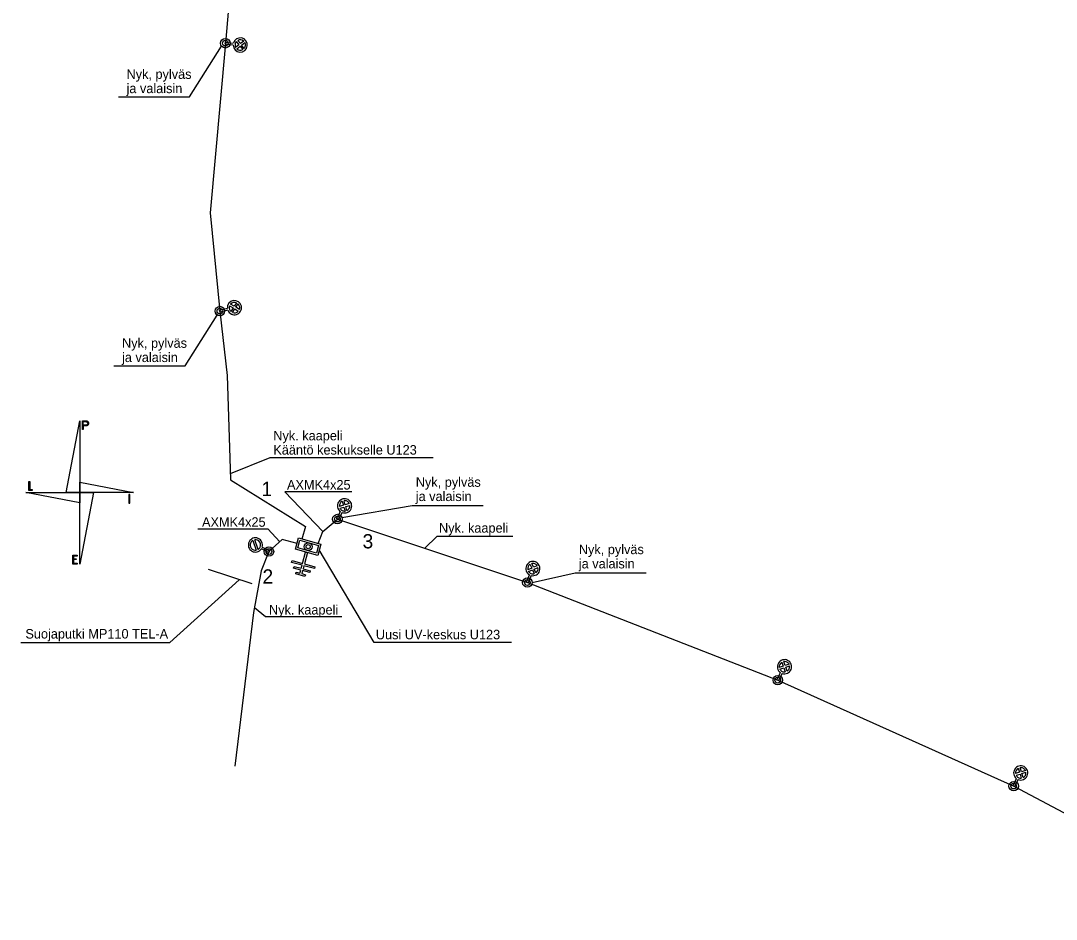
# Model space of a CAD drawing. Extents: x 25497852 to 25498297, y 6686544 to 6687252.
# Drawn here: x 25497911.2 to 25498074.6, y 6686966.9 to 6687108.7 of the extents above; entities that cross this region are included whole.
import ezdxf

# ---------------------------------------------------------------- set-up
doc = ezdxf.new("R2010")
doc.units = 0
for name, color, linetype in [('KayttoOikeusYksikko_piste_tunnus', 7, 'Continuous'), ('KiinteistoNimi', 7, 'Continuous'), ('Raja', 7, 'Continuous'), ('Rajamerkki_tonttipyykki', 7, 'Continuous'), ('Rasitealue', 7, 'Continuous'), ('Rasiteviiva', 7, 'Continuous'), ('Taso 1', 7, 'Continuous'), ('VuokraAlue', 7, 'Continuous')]:
    doc.layers.add(name, color=color, linetype=linetype)

msp = doc.modelspace()

# ---------------------------------------------------------------- linework, layer by layer
at = {"layer": 'KayttoOikeusYksikko_piste_tunnus'}
for p, q in [((25497945.83, 6687105.07), (25497945.42, 6687105.59)), ((25497943.43, 6687104.98), (25497943.47, 6687105.28)), ((25497944.68, 6687104.84), (25497943.43, 6687104.98)), ((25497943.47, 6687105.28), (25497944.71, 6687105.13)), ((25497945.59, 6687104.88), (25497945.08, 6687104.47)), ((25497945.18, 6687105.4), (25497945.59, 6687104.88)), ((25497945.26, 6687104.24), (25497945.78, 6687104.65)), ((25497945.78, 6687104.65), (25497946.19, 6687104.13)), ((25497946.35, 6687105.48), (25497945.83, 6687105.07)), ((25497946.02, 6687104.83), (25497946.53, 6687105.24)), ((25497946.43, 6687104.31), (25497946.02, 6687104.83)), ((25497942.55, 6687063), (25497943.77, 6687063.29)), ((25497944.13, 6687063.7), (25497944.69, 6687063.35)), ((25497944.85, 6687063.61), (25497944.28, 6687063.95)), ((25497944.69, 6687063.35), (25497944.34, 6687062.79)), ((25497944.59, 6687062.63), (25497944.94, 6687063.19)), ((25497945.19, 6687064.17), (25497944.85, 6687063.61)), ((25497944.94, 6687063.19), (25497945.5, 6687062.84)), ((25497945.1, 6687063.45), (25497945.45, 6687064.01)), ((25497945.66, 6687063.1), (25497945.1, 6687063.45)), ((25497942.62, 6687062.71), (25497942.55, 6687063)), ((25497943.84, 6687063), (25497942.62, 6687062.71)), ((25497962.08, 6687032.21), (25497961.45, 6687032.02)), ((25497961.89, 6687032.84), (25497962.08, 6687032.21)), ((25497962.37, 6687032.29), (25497962.18, 6687032.93)), ((25497963, 6687032.48), (25497962.37, 6687032.29)), ((25497962.45, 6687032.01), (25497963.09, 6687032.19)), ((25497962.64, 6687031.37), (25497962.45, 6687032.01)), ((25497961, 6687030.1), (25497961.6, 6687031.2)), ((25497961.86, 6687031.06), (25497961.26, 6687029.96)), ((25497961.53, 6687031.74), (25497962.16, 6687031.92)), ((25497962.16, 6687031.92), (25497962.35, 6687031.29)), ((25497961.26, 6687029.96), (25497961, 6687030.1)), ((25497947.8, 6687026.66), (25497948.32, 6687025.13)), ((25497948.61, 6687025.22), (25497948.08, 6687026.76)), ((25497949.27, 6687025.59), (25497950.4, 6687025.03)), ((25497950.26, 6687024.76), (25497949.14, 6687025.32)), ((25497950.4, 6687025.03), (25497950.26, 6687024.76)), ((25497991.79, 6687022.29), (25497991.18, 6687022.03)), ((25497991.52, 6687022.89), (25497991.79, 6687022.29)), ((25497992.06, 6687022.41), (25497991.8, 6687023.01)), ((25497992.67, 6687022.67), (25497992.06, 6687022.41)), ((25497992.18, 6687022.13), (25497992.79, 6687022.39)), ((25497990.97, 6687020.06), (25497991.43, 6687021.23)), ((25497991.71, 6687021.12), (25497991.25, 6687019.95)), ((25497991.3, 6687021.75), (25497991.91, 6687022.01)), ((25497991.91, 6687022.01), (25497992.17, 6687021.41)), ((25497992.44, 6687021.52), (25497992.18, 6687022.13)), ((25497991.25, 6687019.95), (25497990.97, 6687020.06)), ((25498031.77, 6687006.91), (25498031.56, 6687007.54)), ((25498031.49, 6687006.82), (25498030.86, 6687006.61)), ((25498030.95, 6687006.32), (25498031.58, 6687006.53)), ((25498031.27, 6687007.44), (25498031.49, 6687006.82)), ((25498031.58, 6687006.53), (25498031.79, 6687005.91)), ((25498032.4, 6687007.13), (25498031.77, 6687006.91)), ((25498031.87, 6687006.63), (25498032.49, 6687006.84)), ((25498032.08, 6687006), (25498031.87, 6687006.63)), ((25498030.49, 6687004.67), (25498031.05, 6687005.79)), ((25498030.76, 6687004.53), (25498030.49, 6687004.67)), ((25498031.32, 6687005.66), (25498030.76, 6687004.53)), ((25498068.77, 6686990.06), (25498068.14, 6686989.87)), ((25498068.23, 6686989.58), (25498068.86, 6686989.78)), ((25498068.58, 6686990.69), (25498068.77, 6686990.06)), ((25498068.86, 6686989.78), (25498069.05, 6686989.14)), ((25498069.06, 6686990.15), (25498068.87, 6686990.78)), ((25498069.69, 6686990.34), (25498069.06, 6686990.15)), ((25498069.15, 6686989.86), (25498069.78, 6686990.06)), ((25498069.34, 6686989.23), (25498069.15, 6686989.86)), ((25498067.71, 6686987.94), (25498068.3, 6686989.05)), ((25498067.98, 6686987.8), (25498067.71, 6686987.94)), ((25498068.57, 6686988.91), (25498067.98, 6686987.8))]:
    msp.add_line(p, q, dxfattribs=at)
for centre, radius, start, end in [((25497945.8, 6687104.86), 1.12, 353.4004, 165.7381), ((25497945.8, 6687104.86), 0.825, 48.876, 117.9247), ((25497945.8, 6687104.86), 1.12, 181.0626, 353.4004), ((25497945.8, 6687104.86), 0.825, 173.4004, 207.9247), ((25497945.8, 6687104.86), 0.825, 138.876, 173.4004), ((25497945.8, 6687104.86), 0.825, 228.876, 297.9247), ((25497945.8, 6687104.86), 0.825, 318.876, 353.4004), ((25497945.8, 6687104.86), 0.825, 353.4004, 27.9247), ((25497944.89, 6687063.4), 1.12, 13.2418, 185.5795), ((25497944.89, 6687063.4), 1.12, 200.904, 13.2418), ((25497944.89, 6687063.4), 0.825, 158.7175, 193.2418), ((25497944.89, 6687063.4), 0.825, 193.2418, 227.7661), ((25497944.89, 6687063.4), 0.825, 68.7175, 137.7661), ((25497944.89, 6687063.4), 0.825, 13.2418, 47.7661), ((25497944.89, 6687063.4), 0.825, 338.7175, 13.2418), ((25497944.89, 6687063.4), 0.825, 248.7175, 317.7661), ((25497962.27, 6687032.11), 1.12, 61.3434, 233.6812), ((25497962.27, 6687032.11), 0.825, 116.8191, 185.8678), ((25497962.27, 6687032.11), 1.12, 249.0057, 61.3434), ((25497962.27, 6687032.11), 0.825, 61.3434, 95.8678), ((25497962.27, 6687032.11), 0.825, 296.8191, 5.8678), ((25497962.27, 6687032.11), 0.825, 26.8191, 61.3434), ((25497962.27, 6687032.11), 0.825, 206.8191, 241.3434), ((25497962.27, 6687032.11), 0.825, 241.3434, 275.8678), ((25497948.2, 6687025.94), 1.12, 341.5217, 153.8595), ((25497948.2, 6687025.94), 1.12, 153.8595, 326.1972), ((25497948.2, 6687025.94), 0.825, 153.8595, 278.3838), ((25497948.2, 6687025.94), 0.825, 119.3352, 153.8595), ((25497948.2, 6687025.94), 0.825, 333.8595, 98.3838), ((25497948.2, 6687025.94), 0.825, 299.3352, 333.8595), ((25497991.98, 6687022.21), 1.12, 68.4031, 240.7408), ((25497991.98, 6687022.21), 0.825, 123.8788, 192.9274), ((25497991.98, 6687022.21), 1.12, 256.0653, 68.4031), ((25497991.98, 6687022.21), 0.825, 68.4031, 102.9274), ((25497991.98, 6687022.21), 0.825, 33.8788, 68.4031), ((25497991.98, 6687022.21), 0.825, 303.8788, 12.9274), ((25497991.98, 6687022.21), 0.825, 213.8788, 248.4031), ((25497991.98, 6687022.21), 0.825, 248.4031, 282.9274), ((25498031.68, 6687006.72), 1.12, 63.6694, 236.0071), ((25498031.68, 6687006.72), 1.12, 251.3316, 63.6694), ((25498031.68, 6687006.72), 0.825, 63.6694, 98.1937), ((25498031.68, 6687006.72), 0.825, 29.145, 63.6694), ((25498031.68, 6687006.72), 0.825, 119.145, 188.1937), ((25498031.68, 6687006.72), 0.825, 209.145, 243.6694), ((25498031.68, 6687006.72), 0.825, 243.6694, 278.1937), ((25498031.68, 6687006.72), 0.825, 299.145, 8.1937), ((25498068.96, 6686989.96), 1.12, 61.9449, 234.2826), ((25498068.96, 6686989.96), 0.825, 117.4206, 186.4692), ((25498068.96, 6686989.96), 0.825, 207.4206, 241.9449), ((25498068.96, 6686989.96), 1.12, 249.6071, 61.9449), ((25498068.96, 6686989.96), 0.825, 61.9449, 96.4692), ((25498068.96, 6686989.96), 0.825, 297.4206, 6.4692), ((25498068.96, 6686989.96), 0.825, 27.4206, 61.9449), ((25498068.96, 6686989.96), 0.825, 241.9449, 276.4692)]:
    msp.add_arc(centre, radius, start, end, dxfattribs=at)
at = {"layer": 'KiinteistoNimi'}
for centre, radius in [((25497943.45, 6687105.13), 0.75), ((25497943.45, 6687105.13), 0.45), ((25497942.59, 6687062.86), 0.75), ((25497942.59, 6687062.86), 0.45), ((25497961.13, 6687030.03), 0.75), ((25497961.13, 6687030.03), 0.45), ((25497950.33, 6687024.9), 0.75), ((25497950.33, 6687024.9), 0.45), ((25497991.11, 6687020.01), 0.75), ((25497991.11, 6687020.01), 0.45), ((25498030.62, 6687004.6), 0.75), ((25498030.62, 6687004.6), 0.45), ((25498067.85, 6686987.87), 0.75), ((25498067.85, 6686987.87), 0.45)]:
    msp.add_circle(centre, radius, dxfattribs=at)
at = {"layer": 'Raja'}
msp.add_line((25497947.71, 6687019.79), (25497940.77, 6687022.09), dxfattribs=at)
at = {"layer": 'Rajamerkki_tonttipyykki'}
for p, q in [((25497912.44, 6687035.95), (25497912.58, 6687035.95)), ((25497912.44, 6687034.56), (25497912.44, 6687035.95)), ((25497912.58, 6687035.95), (25497912.58, 6687034.7)), ((25497912.99, 6687034.56), (25497912.44, 6687034.56)), ((25497912.58, 6687034.7), (25497912.99, 6687034.7)), ((25497912.99, 6687034.7), (25497912.99, 6687034.56)), ((25497919.37, 6687024.32), (25497920.06, 6687024.32)), ((25497919.37, 6687022.93), (25497919.37, 6687024.32)), ((25497920.06, 6687024.18), (25497919.51, 6687024.18)), ((25497919.51, 6687024.18), (25497919.51, 6687023.76)), ((25497920.06, 6687024.32), (25497920.06, 6687024.18)), ((25497955.64, 6687023.03), (25497956.12, 6687024.82)), ((25497956.41, 6687024.74), (25497955.93, 6687022.96)), ((25497956.12, 6687024.82), (25497956.41, 6687024.74)), ((25497920.06, 6687022.93), (25497919.37, 6687022.93)), ((25497919.51, 6687023.76), (25497919.92, 6687023.76)), ((25497919.92, 6687023.62), (25497919.51, 6687023.62)), ((25497919.51, 6687023.62), (25497919.51, 6687023.07)), ((25497919.51, 6687023.07), (25497920.06, 6687023.07)), ((25497919.92, 6687023.76), (25497919.92, 6687023.62)), ((25497920.06, 6687023.07), (25497920.06, 6687022.93)), ((25497953.89, 6687023.19), (25497953.97, 6687023.48)), ((25497955.56, 6687022.74), (25497953.89, 6687023.19)), ((25497953.97, 6687023.48), (25497955.64, 6687023.03)), ((25497954.23, 6687022.27), (25497954.31, 6687022.56)), ((25497955.35, 6687021.97), (25497954.23, 6687022.27)), ((25497954.31, 6687022.56), (25497955.43, 6687022.26)), ((25497955.43, 6687022.26), (25497955.56, 6687022.74)), ((25497955.85, 6687022.67), (25497955.72, 6687022.18)), ((25497955.72, 6687022.18), (25497956.84, 6687021.88)), ((25497957.51, 6687022.22), (25497955.85, 6687022.67)), ((25497955.93, 6687022.96), (25497957.59, 6687022.51)), ((25497957.59, 6687022.51), (25497957.51, 6687022.22)), ((25497954.56, 6687021.36), (25497954.64, 6687021.64)), ((25497956.01, 6687020.96), (25497954.56, 6687021.36)), ((25497954.64, 6687021.64), (25497955.22, 6687021.49)), ((25497955.22, 6687021.49), (25497955.35, 6687021.97)), ((25497955.64, 6687021.89), (25497955.51, 6687021.41)), ((25497955.51, 6687021.41), (25497956.09, 6687021.25)), ((25497956.76, 6687021.59), (25497955.64, 6687021.89)), ((25497956.09, 6687021.25), (25497956.01, 6687020.96)), ((25497956.84, 6687021.88), (25497956.76, 6687021.59))]:
    msp.add_line(p, q, dxfattribs=at)
for points in [[(25497918.33, 6687034.22), (25497920.48, 6687045.54), (25497920.48, 6687034.22)], [(25497920.48, 6687035.83), (25497928.97, 6687034.22), (25497920.48, 6687034.22)], [(25497920.48, 6687032.61), (25497911.99, 6687034.22), (25497920.48, 6687034.22)], [(25497922.63, 6687034.22), (25497920.48, 6687022.9), (25497920.48, 6687034.22)]]:
    msp.add_lwpolyline(points, close=True, dxfattribs=at)
for points in [[(25497920.9, 6687044.16), (25497920.9, 6687045.55), (25497921.46, 6687045.55)], [(25497921.04, 6687044.86), (25497921.04, 6687045.41), (25497921.46, 6687045.41)], [(25497921.46, 6687045.55), (25497921.5, 6687045.55), (25497921.54, 6687045.54), (25497921.58, 6687045.53), (25497921.62, 6687045.51), (25497921.66, 6687045.49), (25497921.7, 6687045.47), (25497921.73, 6687045.44), (25497921.76, 6687045.41), (25497921.79, 6687045.38), (25497921.81, 6687045.34), (25497921.83, 6687045.3), (25497921.85, 6687045.26), (25497921.86, 6687045.22), (25497921.87, 6687045.18), (25497921.87, 6687045.14), (25497921.87, 6687045.09), (25497921.86, 6687045.05), (25497921.85, 6687045.01), (25497921.83, 6687044.97), (25497921.81, 6687044.93), (25497921.79, 6687044.89), (25497921.76, 6687044.86), (25497921.73, 6687044.83), (25497921.7, 6687044.8), (25497921.66, 6687044.78), (25497921.62, 6687044.76), (25497921.58, 6687044.74), (25497921.54, 6687044.73), (25497921.5, 6687044.72), (25497921.46, 6687044.72)], [(25497921.46, 6687045.41), (25497921.48, 6687045.41), (25497921.51, 6687045.4), (25497921.54, 6687045.4), (25497921.57, 6687045.39), (25497921.59, 6687045.37), (25497921.62, 6687045.36), (25497921.64, 6687045.34), (25497921.66, 6687045.32), (25497921.68, 6687045.3), (25497921.69, 6687045.27), (25497921.71, 6687045.25), (25497921.72, 6687045.22), (25497921.73, 6687045.19), (25497921.73, 6687045.16), (25497921.73, 6687045.14), (25497921.73, 6687045.11), (25497921.73, 6687045.08), (25497921.72, 6687045.05), (25497921.71, 6687045.02), (25497921.69, 6687045), (25497921.68, 6687044.97), (25497921.66, 6687044.95), (25497921.64, 6687044.93), (25497921.62, 6687044.91), (25497921.59, 6687044.9), (25497921.57, 6687044.88), (25497921.54, 6687044.87), (25497921.51, 6687044.87), (25497921.48, 6687044.86), (25497921.46, 6687044.86)], [(25497921.46, 6687044.72), (25497921.04, 6687044.72), (25497921.04, 6687044.16), (25497920.9, 6687044.16)], [(25497921.46, 6687044.86), (25497921.04, 6687044.86)], [(25497928.22, 6687032.52), (25497928.36, 6687032.52), (25497928.36, 6687033.92), (25497928.22, 6687033.92), (25497928.22, 6687032.52)]]:
    msp.add_lwpolyline(points, dxfattribs=at)
at = {"layer": 'Rasitealue'}
for p, q in [((25497961.13, 6687030.03), (25497991.11, 6687020.01)), ((25497991.11, 6687020.01), (25498030.62, 6687004.6)), ((25498030.62, 6687004.6), (25498067.85, 6686987.87)), ((25498067.85, 6686987.87), (25498107.28, 6686966.85))]:
    msp.add_line(p, q, dxfattribs=at)
for points in [[(25497940.63, 6687135.56), (25497945.62, 6687130.39), (25497943.46, 6687105.16)], [(25497943.45, 6687105.13), (25497941.06, 6687078.34), (25497942.59, 6687062.85)], [(25497942.59, 6687062.86), (25497943.72, 6687052.67), (25497944.15, 6687039.66), (25497944.26, 6687036.24), (25497956.12, 6687028.87), (25497955.54, 6687026.88)], [(25497958.1, 6687026.15), (25497958.85, 6687028.05), (25497961.13, 6687030.03)], [(25497954.76, 6687026.17), (25497952.44, 6687026.79), (25497950.33, 6687024.9)], [(25497950.33, 6687024.9), (25497949.1, 6687021.84), (25497947.87, 6687015.26), (25497944.96, 6686991.03)]]:
    msp.add_lwpolyline(points, dxfattribs=at)
at = {"layer": 'Taso 1'}
for points in [[(25497926.59, 6687096.67), (25497937.82, 6687096.67), (25497942.85, 6687104.68)], [(25497925.88, 6687054.21), (25497937.11, 6687054.21), (25497942.14, 6687062.22)], [(25497976.24, 6687039.7), (25497950.48, 6687039.7), (25497944.23, 6687037.19)], [(25497963.4, 6687034.3), (25497952.86, 6687034.3), (25497958.85, 6687028.05)], [(25497984.15, 6687032.1), (25497972.92, 6687032.1), (25497961.84, 6687030.22)], [(25497939.1, 6687028.49), (25497950.13, 6687028.49), (25497952.05, 6687026.45)], [(25497988.79, 6687027.3), (25497976.82, 6687027.3), (25497974.91, 6687025.42)], [(25497988.58, 6687010.52), (25497966.91, 6687010.52), (25497958.27, 6687025.17)], [(25498009.88, 6687021.47), (25497998.65, 6687021.47), (25497991.86, 6687019.96)], [(25497911.16, 6687010.52), (25497934.71, 6687010.52), (25497945.65, 6687020.44)], [(25497961.83, 6687014.57), (25497949.79, 6687014.57), (25497948.03, 6687016.03)]]:
    msp.add_lwpolyline(points, dxfattribs=at)
at = {"layer": 'VuokraAlue'}
for p, q in [((25497954.51, 6687025.28), (25497955.01, 6687027.06)), ((25497954.88, 6687025.48), (25497955.22, 6687026.69)), ((25497957.81, 6687024.65), (25497954.88, 6687025.48)), ((25497955.01, 6687027.06), (25497958.52, 6687026.06)), ((25497955.22, 6687026.69), (25497958.15, 6687025.86)), ((25497958.15, 6687025.86), (25497957.81, 6687024.65)), ((25497958.52, 6687026.06), (25497958.02, 6687024.28)), ((25497958.02, 6687024.28), (25497954.51, 6687025.28))]:
    msp.add_line(p, q, dxfattribs=at)
for radius in [0.625, 0.325]:
    msp.add_circle((25497956.52, 6687025.67), radius, dxfattribs=at)

# ---------------------------------------------------------------- texts
at = {"layer": 'Rasiteviiva'}
for s, height, p in [('Nyk, pylväs', 1.5, (25497927.86, 6687099.51)), ('ja valaisin', 1.5, (25497927.86, 6687097.26)), ('Nyk, pylväs', 1.5, (25497927.15, 6687057.06)), ('ja valaisin', 1.5, (25497927.15, 6687054.81)), ('Nyk. kaapeli', 1.5, (25497951.02, 6687042.45)), ('Kääntö keskukselle U123', 1.5, (25497951.02, 6687040.2)), ('1', 2.25, (25497949.14, 6687033.66)), ('AXMK4x25', 1.5, (25497953.18, 6687034.69)), ('Nyk, pylväs', 1.5, (25497973.5, 6687035.12)), ('ja valaisin', 1.5, (25497973.5, 6687032.87)), ('AXMK4x25', 1.5, (25497939.77, 6687028.81)), ('Nyk. kaapeli', 1.5, (25497977.17, 6687027.88)), ('3', 2.25, (25497965.11, 6687025.4)), ('Nyk, pylväs', 1.5, (25497999.23, 6687024.49)), ('ja valaisin', 1.5, (25497999.23, 6687022.24)), ('2', 2.25, (25497949.32, 6687019.84)), ('Nyk. kaapeli', 1.5, (25497950.34, 6687014.96)), ('Suojaputki MP110 TEL-A', 1.5, (25497911.9, 6687011.17)), ('Uusi UV-keskus U123', 1.5, (25497967.2, 6687011.05))]:
    msp.add_text(s, height=height, dxfattribs=at).set_placement(p)

doc.saveas('drawing.dxf')
